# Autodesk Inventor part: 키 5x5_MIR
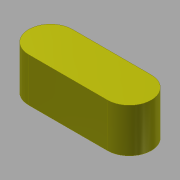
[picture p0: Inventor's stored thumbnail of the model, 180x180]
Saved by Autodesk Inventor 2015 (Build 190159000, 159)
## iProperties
Created: 2014-10
Part Number: 키 5x5_MIR
Material: 강철, 연강
Document SubType Name: Modeling
Designer: User
Mass: 2.54015 g
Surface Area: 2.9781 cm^2
Volume: 0.323175 cm^3
Density: 7.86 g/cm^3
Appearance: 강철
Author: SeoGD™ [www.esajin.kr]
Revision Number: 1
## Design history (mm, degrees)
derived "키 5x5.ipt"
  sketch "스케치1"
    geometry: L1 (4.5, -2.5)-(-4.5, -2.5) reference; L2 (-4.5, 2.5)-(4.5, 2.5) reference; A1 r 2.5 centre (-4.5, 0) between (-4.5, 2.5) and (-4.5, -2.5) reference; A2 r 2.5 centre (4.5, 0) between (4.5, -2.5) and (4.5, 2.5) reference; 2 further points
    dimensions: "d0" = 10 dimension on point (0, 0) L1.start L1.end L1 L2.start A1.centre A1 L2.end L2 A2.centre A2 point (0, -2.5)
feature "솔리드1::키 5x5.ipt" dims "d0" = 10
tag "피쳐 태그1"
node "솔리드1"
